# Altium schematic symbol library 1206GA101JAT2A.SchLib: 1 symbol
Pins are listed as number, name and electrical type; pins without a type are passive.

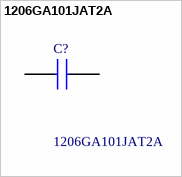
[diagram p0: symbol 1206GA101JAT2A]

## 1206GA101JAT2A
designator C?
Multilayer Ceramic Capacitors MLCC - SMD/SMT 2KV 100pF C0G 1206 5% Tol HV; Manufacturer_Name: Kyocera AVX; Geometry.Height: 1.8mm
footprint CAPC3316X180N
pins: 1, 2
